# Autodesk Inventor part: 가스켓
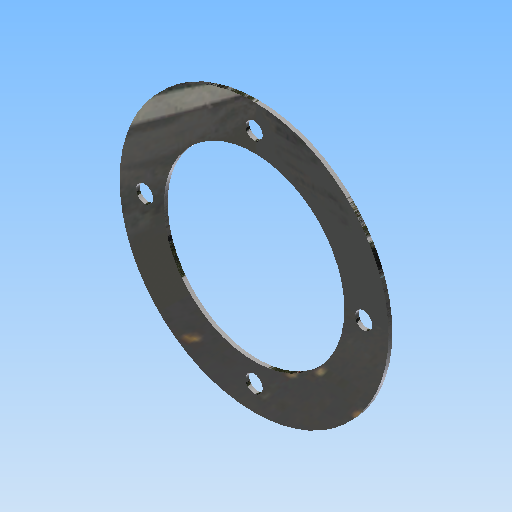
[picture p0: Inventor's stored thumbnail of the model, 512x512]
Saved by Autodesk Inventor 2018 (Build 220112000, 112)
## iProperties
Created: 2024-02
Part Number: 가스켓
Material: 스테인리스강
Document SubType Name: Modeling
Designer: mdu-01
Density: 1 g/cm^3
Appearance: 반광택
Author: mdu-01
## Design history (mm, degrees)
sketch "스케치1"
  geometry: C1 r 35 at (0, 0); C2 r 23.5 at (0, 0); C3 r 2.25 at (0, 28.5); C4 r 2.25 at (28.5, 0); C5 r 2.25 at (-28.5, 0); C6 r 2.25 at (0, -28.5); A1 r 28.5 centre (0, 0) between (0, 28.5) and (28.5, 0); 1 further point
  constraints: 7 centre point, 4 point on circle, 3 coincident, 3 equal radius, 2 horizontal alignment, 2 vertical alignment
  dimensions: "d0" = 70 diameter of C1; "d1" = 47 diameter of C2; "d2" = 57 diameter of A1; "d3" = 4.5 diameter of C3
extrude "돌출1" new body sketch "스케치1" distance "d4" = 1; taper "d5" = 0 deg
node "솔리드1"
